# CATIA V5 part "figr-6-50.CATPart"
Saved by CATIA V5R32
Part number: Part1
Bounding box of the stored display mesh (mm): x -54.76 to 54.76, y -32.885 to 32.885, z 0 to 59
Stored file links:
  D:\PROJECTS\Project 2022\CATIA V5 6R 2022\Resources\Part Files\c06_catia_v5_6r2022_prt\figr-6-50.CATPart
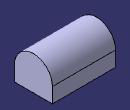
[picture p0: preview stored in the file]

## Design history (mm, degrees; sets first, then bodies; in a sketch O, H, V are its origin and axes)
Body1 (main body)
  Sketch1 on xy-plane, origin (0, 0, 0), H (1, 0, 0), V (0, 1, 0)
    line L1 (-54.7599, 32.8853) -> (54.7599, 32.8853)
    line L2 (54.7599, 32.8853) -> (54.7599, -32.8853)
    line L3 (54.7599, -32.8853) -> (-54.7599, -32.8853)
    line L4 (-54.7599, -32.8853) -> (-54.7599, 32.8853)
    axis line L5 (54.7599, -32.8853) -> (-54.7599, 32.8853)
    horizontal: L1 H, L3 H
    vertical: L2 V, L4 V
    midpoint: O L5
  Pad1: profile Sketch1, direction (0, 0, 1), length 59
  TritangentFillet1: Face1 face of Pad1, Face2 face of Pad1, RemoveFace face of Pad1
